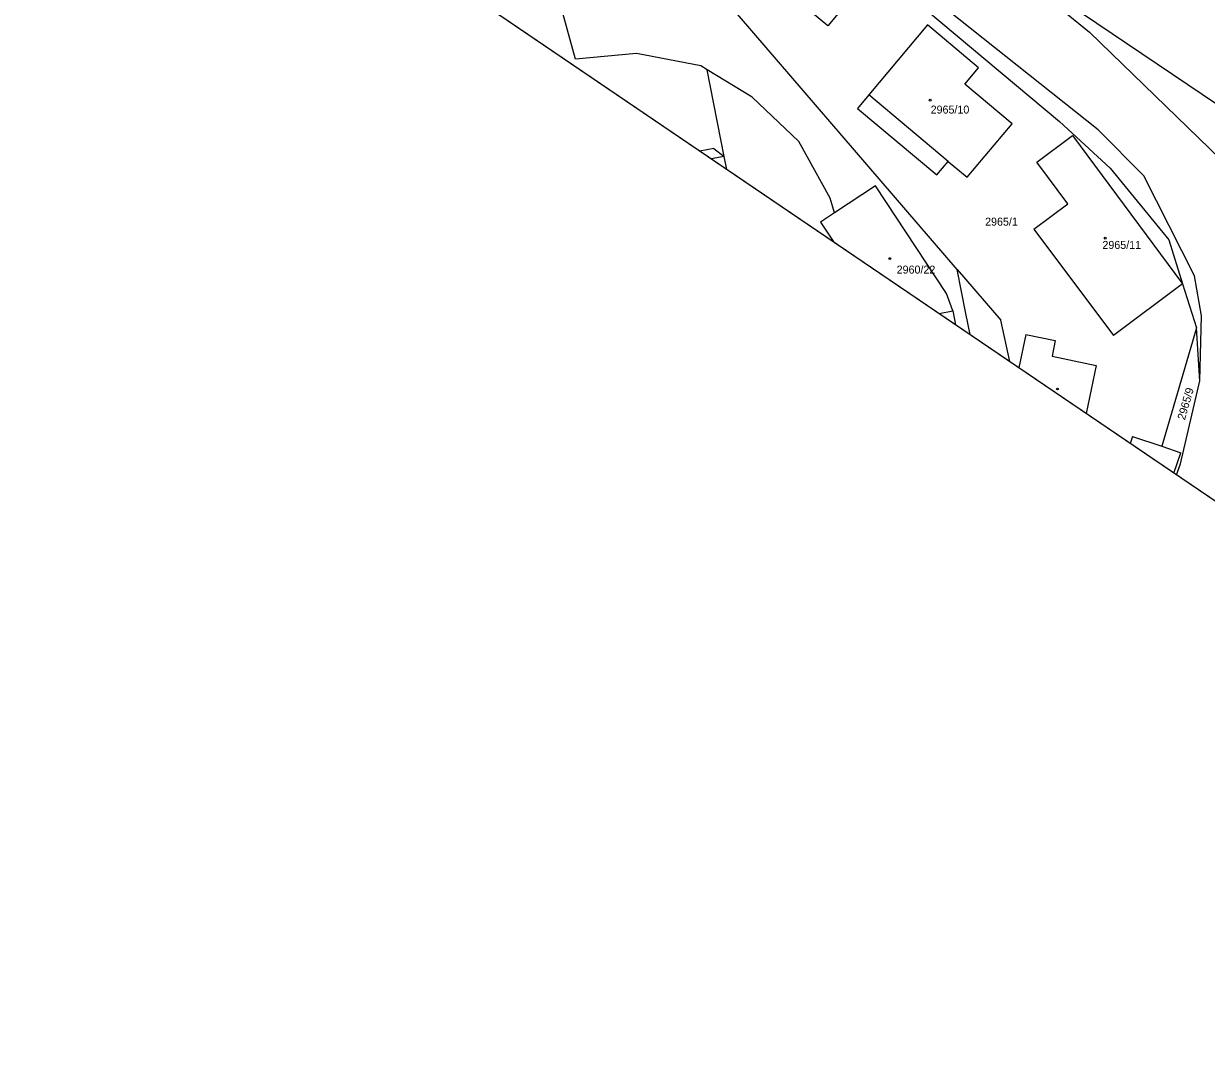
# Model space of a CAD drawing. Extents: x -621058 to -620023, y -1122866 to -1122030.
# Drawn here: x -620566.7 to -620345, y -1122865.7 to -1122671.6 of the extents above; entities that cross this region are included whole.
import ezdxf

# ---------------------------------------------------------------- set-up
doc = ezdxf.new("R2010")
doc.units = 0
for name, color, linetype in [('RÁMY', 7, 'Continuous'), ('Vrstva 55', 7, 'Continuous'), ('Vrstva 56', 7, 'Continuous'), ('Vrstva 57', 7, 'Continuous')]:
    doc.layers.add(name, color=color, linetype=linetype)

msp = doc.modelspace()

# ---------------------------------------------------------------- linework, layer by layer
at = {"layer": 'RÁMY'}
for points in [[(-620974.7, -1122152.91), (-620106.07, -1122742.82), (-620189.51, -1122865.67), (-621058.13, -1122275.76)], [(-620887.83, -1122211.9), (-620106.07, -1122742.82), (-620189.51, -1122865.67), (-620971.26, -1122334.75)]]:
    msp.add_lwpolyline(points, close=True, dxfattribs=at)
at = {"layer": 'Vrstva 55'}
for p, q in [((-620463.28, -1122678.3), (-620478.32, -1122624.38)), ((-620420.38, -1122629.64), (-620366.98, -1122673.23)), ((-620391.77, -1122717.74), (-620434.88, -1122667.63)), ((-620365.35, -1122691.52), (-620395.68, -1122667.41)), ((-620368.46, -1122669.58), (-620310.57, -1122708.76)), ((-620397.34, -1122671.88), (-620408.32, -1122685)), ((-620387.77, -1122679.92), (-620397.34, -1122671.88)), ((-620366.98, -1122673.23), (-620342.37, -1122697.07)), ((-620451.85, -1122677.25), (-620463.28, -1122678.3)), ((-620439.78, -1122679.56), (-620451.85, -1122677.25)), ((-620438.61, -1122680.28), (-620439.78, -1122679.56)), ((-620435.41, -1122696.52), (-620438.61, -1122680.28)), ((-620430.21, -1122685.42), (-620438.61, -1122680.28)), ((-620390.32, -1122682.97), (-620387.77, -1122679.92)), ((-620408.32, -1122685), (-620410.45, -1122687.55)), ((-620381.44, -1122690.4), (-620390.32, -1122682.97)), ((-620421.46, -1122693.76), (-620430.21, -1122685.42)), ((-620410.45, -1122687.55), (-620395.56, -1122700.01)), ((-620389.88, -1122700.43), (-620381.44, -1122690.4)), ((-620356.78, -1122700.2), (-620365.35, -1122691.52)), ((-620415.57, -1122704.35), (-620421.46, -1122693.76)), ((-620376.85, -1122697.59), (-620370.13, -1122692.59)), ((-620370.13, -1122692.59), (-620349.5, -1122720.4)), ((-620435.41, -1122696.52), (-620437.86, -1122697)), ((-620434.92, -1122699), (-620435.41, -1122696.52)), ((-620395.56, -1122700.01), (-620393.43, -1122697.46)), ((-620393.43, -1122697.46), (-620389.88, -1122700.43)), ((-620347.29, -1122718.92), (-620356.78, -1122700.2)), ((-620407.04, -1122702.06), (-620414.76, -1122707.13)), ((-620393.75, -1122722.26), (-620407.04, -1122702.06)), ((-620414.76, -1122707.13), (-620415.57, -1122704.35)), ((-620414.76, -1122707.13), (-620417.37, -1122708.84)), ((-620417.37, -1122708.84), (-620414.89, -1122712.61)), ((-620377.36, -1122710.19), (-620362.45, -1122730.09)), ((-620391.77, -1122717.74), (-620383.57, -1122727.26)), ((-620390.13, -1122725.98), (-620391.77, -1122717.74)), ((-620349.5, -1122720.4), (-620362.45, -1122730.09)), ((-620349.5, -1122720.4), (-620346.9, -1122728.66)), ((-620345.94, -1122726.44), (-620347.29, -1122718.92)), ((-620392.56, -1122725.51), (-620393.75, -1122722.26)), ((-620395.15, -1122726.01), (-620392.56, -1122725.51)), ((-620392.56, -1122725.51), (-620392.06, -1122728.11)), ((-620389.35, -1122729.95), (-620390.13, -1122725.98)), ((-620346.26, -1122738.61), (-620345.94, -1122726.44)), ((-620381.9, -1122735.01), (-620383.57, -1122727.26)), ((-620346.9, -1122728.66), (-620353.41, -1122750.9)), ((-620346.26, -1122738.61), (-620346.9, -1122728.66)), ((-620378.87, -1122729.94), (-620380.18, -1122736.18)), ((-620378.87, -1122729.94), (-620373.38, -1122731.07)), ((-620373.38, -1122731.07), (-620373.97, -1122734.01)), ((-620373.97, -1122734.01), (-620365.7, -1122735.74)), ((-620365.7, -1122735.74), (-620367.58, -1122744.74)), ((-620349.91, -1122754.18), (-620346.26, -1122738.61)), ((-620358.86, -1122749.03), (-620359.31, -1122750.35)), ((-620358.86, -1122749.03), (-620353.41, -1122750.9)), ((-620353.41, -1122750.9), (-620349.8, -1122752.13)), ((-620351.12, -1122755.91), (-620349.8, -1122752.13)), ((-620350.63, -1122756.24), (-620349.91, -1122754.18))]:
    msp.add_line(p, q, dxfattribs=at)
for points in [[(-620432.38, -1122643.03), (-620419.73, -1122650.41), (-620372.55, -1122689.97), (-620363.06, -1122698.75), (-620352.08, -1122712.18), (-620349.5, -1122720.4)], [(-620434.7, -1122656.53), (-620427.07, -1122647.39), (-620408.37, -1122662.86), (-620416.01, -1122672.06), (-620434.7, -1122656.53)], [(-620377.36, -1122710.19), (-620370.99, -1122705.44), (-620376.85, -1122697.59)]]:
    msp.add_lwpolyline(points, dxfattribs=at)
at = {"layer": 'Vrstva 56'}
for p, q in [((-620393.43, -1122697.46), (-620408.32, -1122685)), ((-620437.36, -1122695.04), (-620439.99, -1122695.56)), ((-620437.36, -1122695.04), (-620435.41, -1122696.52))]:
    msp.add_line(p, q, dxfattribs=at)
at = {"layer": 'Vrstva 57'}
for centre in [(-620396.83, -1122685.99), (-620363.99, -1122711.85), (-620404.37, -1122715.7), (-620372.96, -1122740.15)]:
    msp.add_circle(centre, 0.175, dxfattribs=at)

# ---------------------------------------------------------------- texts
for s, p in [('2965/10', (-620396.73, -1122688.5)), ('2965/1', (-620386.52, -1122709.52)), ('2965/11', (-620364.53, -1122713.88)), ('2960/22', (-620403.1, -1122718.51))]:
    msp.add_text(s, height=1.5, dxfattribs=at).set_placement(p)
msp.add_text('2965/9', height=1.5, rotation=73.8221, dxfattribs=at).set_placement((-620349.08, -1122746.06))

doc.saveas('drawing.dxf')
